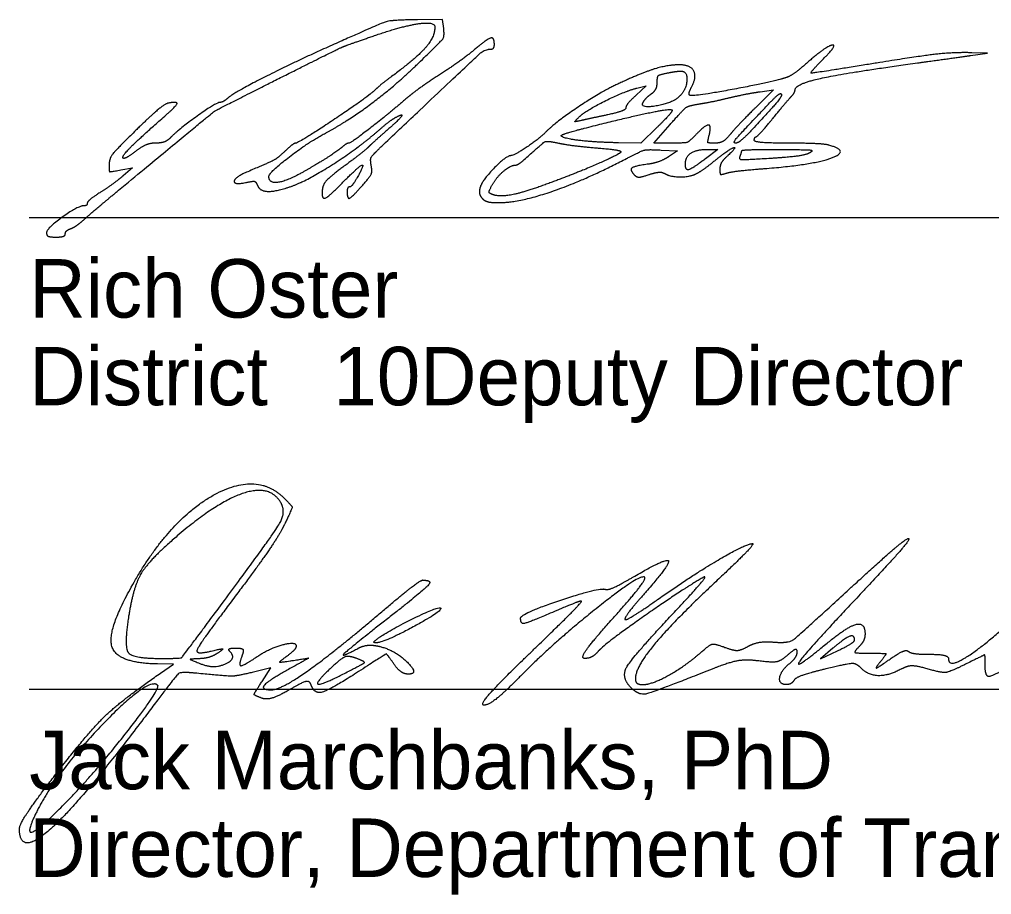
# Model space of a CAD drawing. Extents: x 39.8 to 73.8, y 13 to 35.
# Drawn here: x 64.74 to 67.068, y 18.351 to 20.447 of the extents above; entities that cross this region are included whole.
import ezdxf

# ---------------------------------------------------------------- set-up
doc = ezdxf.new("R2010")
doc.units = 0
doc.layers.add('SH_Data', color=7, linetype='Continuous')
doc.layers.add('SH_Text', color=7, linetype='Continuous')

msp = doc.modelspace()

# ---------------------------------------------------------------- linework, layer by layer
at = {"layer": 'SH_Data'}
for p, q in [((64.763, 19.9729), (68.263, 19.9729)), ((64.763, 18.8435), (68.263, 18.8435))]:
    msp.add_line(p, q, dxfattribs=at)
at = {"layer": 'SH_Text'}
for p, q in [((64.8044, 19.9359), (64.8044, 19.9359)), ((65.2253, 19.0486), (65.2253, 19.0486)), ((65.5906, 18.9587), (65.5906, 18.9587)), ((66.7396, 18.9607), (66.7396, 18.9607)), ((65.9624, 18.9297), (65.9624, 18.9297)), ((65.5458, 18.9171), (65.5458, 18.9171))]:
    msp.add_line(p, q, dxfattribs=at)
for points in [[(65.7556, 20.4251), (65.7531, 20.4469), (65.6931, 20.4462)], [(67.0169, 20.3604), (67.0581, 20.3662), (67.0204, 20.3672)], [(66.2182, 20.2823), (66.2406, 20.2876), (66.2163, 20.2653)], [(66.5132, 20.2738), (66.5457, 20.2786), (66.5019, 20.2352)], [(66.2667, 20.1887), (66.2275, 20.1507), (66.174, 20.1516)], [(66.2994, 20.1507), (66.2585, 20.1507), (66.2977, 20.1952)], [(66.276, 20.1342), (66.3152, 20.1319), (66.2937, 20.1179)], [(66.3869, 20.1357), (66.4121, 20.1357), (66.3826, 20.1134)], [(64.9825, 20.0865), (65.0106, 20.0914), (64.9881, 20.0726)], [(66.6878, 18.941), (66.6583, 18.9154), (66.6989, 18.9351)], [(65.0776, 18.8816), (65.1083, 18.9028), (65.0705, 18.9035)], [(65.3206, 18.8618), (65.3418, 18.8941), (65.3, 18.884)]]:
    msp.add_lwpolyline(points, dxfattribs=at)
for points in [[(65.6931, 20.4462), (65.6306, 20.4455), (65.6042, 20.4373), (65.4681, 20.3762)], [(65.5956, 20.4102), (65.6597, 20.432), (65.7344, 20.442), (65.7344, 20.4287)], [(65.7344, 20.4287), (65.7344, 20.4048), (65.6894, 20.3534), (65.6302, 20.3099)], [(65.6956, 20.3426), (65.7496, 20.395), (65.7578, 20.4062), (65.7556, 20.4251)], [(65.3856, 20.3179), (65.4978, 20.3742), (65.5234, 20.3855), (65.5956, 20.4102)], [(65.8769, 20.3869), (65.8769, 20.4049), (65.8593, 20.4), (65.8276, 20.3732)], [(65.4681, 20.3762), (65.3879, 20.3401), (65.2521, 20.2706), (65.2388, 20.2587)], [(65.6105, 20.1465), (65.8319, 20.3561), (65.8539, 20.3756), (65.8675, 20.3757)], [(65.8276, 20.3732), (65.8114, 20.3595), (65.7745, 20.3331), (65.7456, 20.3144)], [(65.8675, 20.3757), (65.8727, 20.3757), (65.8769, 20.3807), (65.8769, 20.3869)], [(66.6637, 20.3513), (66.7005, 20.3881), (66.671, 20.3828), (66.628, 20.3448)], [(66.7604, 20.3374), (66.64, 20.3178), (66.6314, 20.3191), (66.6637, 20.3513)], [(67.0204, 20.3672), (66.976, 20.3683), (66.8921, 20.3587), (66.7604, 20.3374)], [(66.8902, 20.3428), (66.9372, 20.3493), (66.9942, 20.3572), (67.0169, 20.3604)], [(65.4723, 20.1747), (65.526, 20.2031), (65.6407, 20.2893), (65.6956, 20.3426)], [(66.3195, 20.3382), (66.292, 20.3382), (66.2302, 20.319), (66.1747, 20.2933)], [(66.3495, 20.286), (66.3623, 20.3099), (66.346, 20.3382), (66.3195, 20.3382)], [(66.628, 20.3448), (66.6088, 20.3279), (66.5864, 20.3115), (66.5781, 20.3085)], [(66.5969, 20.2778), (66.5969, 20.2922), (66.7195, 20.3194), (66.8902, 20.3428)], [(64.9769, 20.0377), (65.2015, 20.2237), (65.211, 20.2302), (65.3856, 20.3179)], [(65.6302, 20.3099), (65.6153, 20.2989), (65.5972, 20.284), (65.5899, 20.2768)], [(65.7456, 20.3144), (65.7168, 20.2958), (65.683, 20.2718), (65.6706, 20.2612)], [(66.2669, 20.2964), (66.2669, 20.3099), (66.2722, 20.3148), (66.2903, 20.3185)], [(66.2903, 20.3185), (66.3032, 20.3211), (66.3184, 20.3232), (66.3241, 20.3232)], [(66.3241, 20.3232), (66.3391, 20.3232), (66.3371, 20.2804), (66.3213, 20.2637)], [(66.5781, 20.3085), (66.5507, 20.2984), (66.349, 20.261), (66.3448, 20.2652)], [(66.1747, 20.2933), (66.1327, 20.2739), (66.0242, 20.2015), (65.9985, 20.1758)], [(66.0794, 20.2129), (66.0938, 20.2278), (66.1889, 20.2753), (66.2182, 20.2823)], [(66.2533, 20.2692), (66.2608, 20.2746), (66.2669, 20.2868), (66.2669, 20.2964)], [(66.3448, 20.2652), (66.3425, 20.2675), (66.3447, 20.2768), (66.3495, 20.286)], [(66.5875, 20.2618), (66.5927, 20.2673), (66.5969, 20.2745), (66.5969, 20.2778)], [(65.2388, 20.2587), (65.2323, 20.2529), (65.2237, 20.2482), (65.2197, 20.2482)], [(65.5899, 20.2768), (65.5751, 20.262), (65.4083, 20.1507), (65.401, 20.1507)], [(65.6706, 20.2612), (65.626, 20.2228), (65.5333, 20.1507), (65.5286, 20.1507)], [(66.2163, 20.2653), (66.2029, 20.2531), (66.1919, 20.2397), (66.1919, 20.2356)], [(66.3213, 20.2637), (66.3049, 20.2464), (66.2239, 20.233), (66.2336, 20.2492)], [(66.2336, 20.2492), (66.237, 20.2548), (66.2458, 20.2638), (66.2533, 20.2692)], [(66.3675, 20.2446), (66.3844, 20.2473), (66.4167, 20.2539), (66.4394, 20.2593)], [(66.4394, 20.2593), (66.4621, 20.2647), (66.4953, 20.2712), (66.5132, 20.2738)], [(66.5639, 20.2687), (66.5673, 20.2652), (66.5435, 20.2362), (66.4909, 20.1798)], [(66.5392, 20.2501), (66.5509, 20.2622), (66.5619, 20.2706), (66.5639, 20.2687)], [(66.5444, 20.2107), (66.5629, 20.2334), (66.5823, 20.2564), (66.5875, 20.2618)], [(65.0972, 20.2468), (65.0892, 20.2455), (65.0537, 20.2161), (65.0185, 20.1816)], [(65.0875, 20.2153), (65.1152, 20.2394), (65.1186, 20.2503), (65.0972, 20.2468)], [(65.2197, 20.2482), (65.211, 20.2482), (65.1213, 20.1843), (65.1022, 20.1646)], [(66.0922, 20.1863), (66.189, 20.2111), (66.2985, 20.234), (66.3023, 20.2302)], [(66.1919, 20.2356), (66.1919, 20.2314), (66.1725, 20.2238), (66.1488, 20.2187)], [(66.2977, 20.1952), (66.3301, 20.232), (66.3423, 20.2406), (66.3675, 20.2446)], [(66.5019, 20.2352), (66.4778, 20.2113), (66.4506, 20.1826), (66.4413, 20.1712)], [(66.4547, 20.1507), (66.4469, 20.1507), (66.4683, 20.1759), (66.5392, 20.2501)], [(64.9875, 20.115), (64.9838, 20.1187), (65.0307, 20.1657), (65.0875, 20.2153)], [(65.5994, 20.1809), (65.6138, 20.1936), (65.6319, 20.2075), (65.6397, 20.2118)], [(65.6397, 20.2118), (65.6604, 20.2234), (65.6478, 20.2057), (65.6153, 20.1774)], [(66.0869, 20.2053), (66.0701, 20.2017), (66.0693, 20.2025), (66.0794, 20.2129)], [(66.1488, 20.2187), (66.125, 20.2136), (66.0972, 20.2076), (66.0869, 20.2053)], [(66.3023, 20.2302), (66.3043, 20.2283), (66.2882, 20.2096), (66.2667, 20.1887)], [(66.505, 20.1669), (66.5081, 20.1683), (66.5258, 20.188), (66.5444, 20.2107)], [(66.0373, 20.1677), (66.0353, 20.1697), (66.06, 20.1781), (66.0922, 20.1863)], [(66.3913, 20.1694), (66.3975, 20.1941), (66.3815, 20.1941), (66.358, 20.1693)], [(65.0185, 20.1816), (64.9721, 20.1361), (64.9544, 20.1136), (64.9544, 20.1001)], [(65.1022, 20.1646), (65.0948, 20.1569), (65.0786, 20.1507), (65.0661, 20.1507)], [(65.3369, 20.0707), (65.3369, 20.0802), (65.4327, 20.1538), (65.4723, 20.1747)], [(65.3901, 20.047), (65.4272, 20.0597), (65.5537, 20.1407), (65.5994, 20.1809)], [(65.6153, 20.1774), (65.6007, 20.1648), (65.5831, 20.1489), (65.5762, 20.1422)], [(65.9985, 20.1758), (65.9832, 20.1605), (65.9239, 20.1207), (65.9164, 20.1207)], [(66.174, 20.1516), (66.1188, 20.1526), (66.0436, 20.1614), (66.0373, 20.1677)], [(66.358, 20.1693), (66.3434, 20.1539), (66.3332, 20.1507), (66.2994, 20.1507)], [(66.4055, 20.1507), (66.3891, 20.1507), (66.3872, 20.1531), (66.3913, 20.1694)], [(66.4413, 20.1712), (66.431, 20.1587), (66.4171, 20.1507), (66.4055, 20.1507)], [(66.4909, 20.1798), (66.4759, 20.1638), (66.4596, 20.1507), (66.4547, 20.1507)], [(66.4994, 20.1575), (66.4994, 20.1613), (66.5019, 20.1655), (66.505, 20.1669)], [(65.0661, 20.1507), (65.0531, 20.1507), (65.0323, 20.1422), (65.0174, 20.1309)], [(65.401, 20.1507), (65.3984, 20.1507), (65.3871, 20.1422), (65.376, 20.1319)], [(65.5147, 20.1431), (65.5, 20.1308), (65.4523, 20.1002), (65.4155, 20.0797)], [(65.5286, 20.1507), (65.5259, 20.1507), (65.5197, 20.1472), (65.5147, 20.1431)], [(65.5762, 20.1422), (65.5693, 20.1355), (65.5448, 20.116), (65.5218, 20.099)], [(65.5821, 20.0969), (65.5792, 20.1122), (65.5849, 20.1223), (65.6105, 20.1465)], [(65.9486, 20.1114), (65.9928, 20.1516), (66.0037, 20.1567), (66.0325, 20.1505)], [(66.0325, 20.1505), (66.048, 20.1472), (66.0888, 20.1421), (66.1232, 20.1392)], [(66.1232, 20.1392), (66.1576, 20.1364), (66.1829, 20.1316), (66.1794, 20.1286)], [(66.4079, 20.1112), (66.4405, 20.1376), (66.4598, 20.1422), (66.4319, 20.117)], [(66.58, 20.1506), (66.5357, 20.1506), (66.4994, 20.1538), (66.4994, 20.1575)], [(66.5294, 20.0903), (66.6406, 20.0989), (66.7293, 20.1321), (66.6778, 20.1459)], [(66.6778, 20.1459), (66.6684, 20.1484), (66.6244, 20.1505), (66.58, 20.1506)], [(65.0174, 20.1309), (65.0032, 20.12), (64.9897, 20.1129), (64.9875, 20.115)], [(65.376, 20.1319), (65.3568, 20.1141), (65.3423, 20.1061), (65.2863, 20.0823)], [(65.9164, 20.1207), (65.9054, 20.1207), (65.8484, 20.0622), (65.8431, 20.0456)], [(66.1794, 20.1286), (66.1699, 20.1205), (66.068, 20.0767), (66.0044, 20.0533)], [(66.1937, 20.114), (66.2285, 20.1322), (66.2442, 20.136), (66.276, 20.1342)], [(66.2937, 20.1179), (66.282, 20.1102), (66.2592, 20.1022), (66.2432, 20.1)], [(66.3344, 20.1008), (66.3344, 20.1181), (66.3608, 20.1357), (66.3869, 20.1357)], [(66.4319, 20.117), (66.4237, 20.1095), (66.4169, 20.0967), (66.4169, 20.0886)], [(66.5396, 20.1141), (66.4761, 20.1102), (66.4624, 20.1111), (66.4655, 20.1193)], [(66.4655, 20.1193), (66.4676, 20.1249), (66.4694, 20.1308), (66.4694, 20.1325)], [(66.4694, 20.1325), (66.4694, 20.1343), (66.509, 20.1356), (66.5575, 20.1354)], [(66.6316, 20.1271), (66.6239, 20.1226), (66.5825, 20.1168), (66.5396, 20.1141)], [(66.5575, 20.1354), (66.6246, 20.1353), (66.6423, 20.1333), (66.6316, 20.1271)], [(64.9544, 20.1001), (64.9544, 20.0827), (64.9562, 20.0818), (64.9825, 20.0865)], [(65.5218, 20.099), (65.4819, 20.0695), (65.4644, 20.0488), (65.4644, 20.0312)], [(65.5143, 20.0569), (65.5527, 20.0959), (65.5668, 20.1005), (65.5484, 20.0682)], [(65.5618, 20.0504), (65.5794, 20.0705), (65.5848, 20.0828), (65.5821, 20.0969)], [(65.8704, 20.0481), (65.8801, 20.0669), (65.9144, 20.0975), (65.9261, 20.0979)], [(65.8875, 20.0082), (65.937, 20.0082), (66.0964, 20.0632), (66.1937, 20.114)], [(65.9261, 20.0979), (65.9305, 20.098), (65.9406, 20.1041), (65.9486, 20.1114)], [(66.2432, 20.1), (66.2117, 20.0958), (66.2007, 20.0864), (66.2128, 20.0742)], [(66.3826, 20.1134), (66.3506, 20.0892), (66.3344, 20.0849), (66.3344, 20.1008)], [(66.3606, 20.0776), (66.3689, 20.0817), (66.3902, 20.0969), (66.4079, 20.1112)], [(64.9881, 20.0726), (64.9758, 20.0622), (64.9513, 20.0445), (64.9338, 20.0332)], [(65.2863, 20.0823), (65.255, 20.0691), (65.2529, 20.05), (65.2834, 20.0567)], [(65.4155, 20.0797), (65.3784, 20.059), (65.3369, 20.0542), (65.3369, 20.0707)], [(65.5484, 20.0682), (65.5414, 20.0559), (65.5331, 20.0457), (65.53, 20.0457)], [(66.2128, 20.0742), (66.2181, 20.069), (66.2291, 20.0694), (66.2473, 20.0754)], [(66.2473, 20.0754), (66.262, 20.0802), (66.278, 20.0818), (66.2827, 20.0789)], [(66.2827, 20.0789), (66.2968, 20.0702), (66.3444, 20.0694), (66.3606, 20.0776)], [(66.4169, 20.0886), (66.4169, 20.0768), (66.4202, 20.0749), (66.4338, 20.0791)], [(66.4338, 20.0791), (66.443, 20.0819), (66.4861, 20.087), (66.5294, 20.0903)], [(65.2834, 20.0567), (65.2991, 20.0601), (65.3062, 20.0583), (65.3094, 20.0498)], [(65.3094, 20.0498), (65.3148, 20.0357), (65.3536, 20.0344), (65.3901, 20.047)], [(65.4644, 20.0312), (65.4644, 20.015), (65.4819, 20.024), (65.5143, 20.0569)], [(65.5244, 20.0344), (65.5244, 20.0162), (65.5362, 20.0213), (65.5618, 20.0504)], [(65.53, 20.0457), (65.5269, 20.0457), (65.5244, 20.0406), (65.5244, 20.0344)], [(65.8431, 20.0456), (65.8404, 20.037), (65.8422, 20.0251), (65.8472, 20.0191)], [(65.8713, 20.028), (65.8642, 20.031), (65.864, 20.0358), (65.8704, 20.0481)], [(66.0044, 20.0533), (65.9471, 20.0323), (65.8881, 20.0211), (65.8713, 20.028)], [(64.8944, 19.9679), (64.9047, 19.9773), (64.9418, 20.0087), (64.9769, 20.0377)], [(64.9338, 20.0332), (64.9162, 20.0219), (64.9019, 20.01), (64.9019, 20.0067)], [(64.8943, 20.0007), (64.8801, 20.0007), (64.8044, 19.9461), (64.8044, 19.9359)], [(64.9019, 20.0067), (64.9019, 20.0034), (64.8985, 20.0007), (64.8943, 20.0007)], [(65.8472, 20.0191), (65.8524, 20.0127), (65.8693, 20.0082), (65.8875, 20.0082)], [(64.8625, 19.946), (64.8697, 19.9487), (64.8841, 19.9586), (64.8944, 19.9679)], [(64.8044, 19.9359), (64.8044, 19.9295), (64.8129, 19.9257), (64.8269, 19.9257)], [(64.8269, 19.9257), (64.8393, 19.9257), (64.8494, 19.9291), (64.8494, 19.9334)], [(64.8494, 19.9334), (64.8494, 19.9377), (64.8553, 19.9433), (64.8625, 19.946)], [(65.014, 19.0993), (65.1002, 19.2497), (65.3083, 19.3657), (65.374, 19.3001)], [(65.365, 19.2909), (65.3391, 19.3329), (65.213, 19.2918), (65.1176, 19.2101)], [(65.374, 19.3001), (65.3928, 19.2813), (65.3928, 19.2763), (65.3745, 19.2378)], [(65.2253, 19.0486), (65.3466, 19.212), (65.379, 19.2682), (65.365, 19.2909)], [(65.3745, 19.2378), (65.3635, 19.2148), (65.3118, 19.1393), (65.2596, 19.0699)], [(65.1176, 19.2101), (65.051, 19.1531), (65.0122, 19.089), (65.0011, 19.0177)], [(66.2677, 19.0578), (66.3482, 19.1144), (66.4796, 19.1917), (66.4953, 19.1917)], [(66.4953, 19.1917), (66.5001, 19.1917), (66.4588, 19.149), (66.4035, 19.0969)], [(66.722, 19.0782), (66.797, 19.1473), (66.863, 19.2039), (66.8687, 19.204)], [(66.8687, 19.204), (66.8745, 19.2041), (66.8224, 19.1439), (66.7531, 19.0703)], [(66.2087, 19.1113), (66.2875, 19.1575), (66.2997, 19.1442), (66.2405, 19.0769)], [(65.0705, 18.9035), (64.9726, 18.9052), (64.9491, 18.9863), (65.014, 19.0993)], [(65.6041, 19.0258), (65.6545, 19.0687), (65.7, 19.1039), (65.7052, 19.104)], [(65.7052, 19.104), (65.7301, 19.1045), (65.7067, 19.0789), (65.6208, 19.0116)], [(66.2368, 19.1111), (66.2272, 19.1207), (66.0175, 18.9537), (65.9396, 18.8745)], [(66.3771, 19.1106), (66.328, 19.0828), (66.1397, 18.9506), (66.1265, 18.9347)], [(66.1431, 19.0821), (66.1487, 19.0803), (66.1782, 19.0934), (66.2087, 19.1113)], [(66.159, 19.0107), (66.2053, 19.0624), (66.2403, 19.1076), (66.2368, 19.1111)], [(66.4035, 19.0969), (66.3038, 19.0032), (66.2146, 18.8951), (66.2146, 18.8681)], [(66.3119, 19.0317), (66.358, 19.0809), (66.3874, 19.1165), (66.3771, 19.1106)], [(65.2596, 19.0699), (65.2073, 19.0006), (65.1646, 18.9399), (65.1646, 18.9351)], [(65.9398, 19.0135), (65.94, 19.0241), (66.1274, 19.0872), (66.1431, 19.0821)], [(66.2405, 19.0769), (66.2125, 19.0451), (66.1896, 19.0154), (66.1896, 19.011)], [(66.547, 18.9558), (66.5804, 18.953), (66.6039, 18.9694), (66.722, 19.0782)], [(66.7531, 19.0703), (66.6236, 18.9328), (66.5915, 18.8855), (66.6737, 18.9532)], [(65.0791, 18.9167), (65.1258, 18.9167), (65.1304, 18.9208), (65.2253, 19.0486)], [(65.9624, 18.9297), (66.0334, 18.9981), (66.0888, 19.0542), (66.0853, 19.0542)], [(66.0853, 19.0542), (66.0819, 19.0542), (66.0529, 19.0429), (66.0208, 19.0292)], [(66.1896, 19.011), (66.1896, 19.0065), (66.2247, 19.0276), (66.2677, 19.0578)], [(65.3427, 18.8417), (65.3658, 18.8417), (65.4918, 18.9305), (65.6041, 19.0258)], [(65.5906, 18.9587), (65.611, 18.9766), (65.743, 19.0423), (65.7482, 19.0372)], [(65.7482, 19.0372), (65.7544, 19.031), (65.6118, 18.9542), (65.5941, 18.9542)], [(66.0208, 19.0292), (65.9582, 19.0023), (65.9395, 18.9987), (65.9398, 19.0135)], [(66.2048, 18.8461), (66.1796, 18.8713), (66.2085, 18.9214), (66.3119, 19.0317)], [(66.9646, 18.9151), (66.9646, 18.8923), (67.0599, 18.9538), (67.1302, 19.022)], [(65.0011, 19.0177), (64.9896, 18.9444), (65.0111, 18.9167), (65.0791, 18.9167)], [(65.6208, 19.0116), (65.5276, 18.9386), (65.5061, 18.9171), (65.55, 18.9406)], [(66.0932, 18.9167), (66.0829, 18.9167), (66.1118, 18.9579), (66.159, 19.0107)], [(66.6737, 18.9532), (66.7221, 18.9931), (66.7646, 19.0035), (66.7646, 18.9754)], [(66.7646, 18.9754), (66.7646, 18.9665), (66.7578, 18.9524), (66.7496, 18.9442)], [(65.3087, 18.921), (65.3375, 18.9408), (65.4021, 18.9583), (65.4021, 18.9464)], [(65.5941, 18.9542), (65.5893, 18.9542), (65.5877, 18.9562), (65.5906, 18.9587)], [(66.3721, 18.9317), (66.3924, 18.9497), (66.4052, 18.9523), (66.429, 18.9433)], [(66.484, 18.9454), (66.4974, 18.9529), (66.5257, 18.9576), (66.547, 18.9558)], [(66.7396, 18.9607), (66.7396, 18.9742), (66.7155, 18.965), (66.6878, 18.941)], [(66.6989, 18.9351), (66.7213, 18.9459), (66.7396, 18.9575), (66.7396, 18.9607)], [(65.1646, 18.9351), (65.1646, 18.9304), (65.18, 18.93), (65.1989, 18.9344)], [(65.2146, 18.9297), (65.2043, 18.9227), (65.1846, 18.9166), (65.1708, 18.9161)], [(65.175, 18.9034), (65.2049, 18.8914), (65.2611, 18.916), (65.2437, 18.9334)], [(65.1989, 18.9344), (65.2244, 18.9404), (65.2285, 18.9391), (65.2146, 18.9297)], [(65.2437, 18.9334), (65.2391, 18.9379), (65.2454, 18.9417), (65.2576, 18.9417)], [(65.2576, 18.9417), (65.2721, 18.9417), (65.2773, 18.9352), (65.2725, 18.9229)], [(65.4021, 18.9464), (65.4021, 18.9419), (65.3923, 18.931), (65.3804, 18.9223)], [(65.55, 18.9406), (65.5627, 18.9473), (65.5866, 18.9494), (65.6032, 18.9452)], [(65.6362, 18.9038), (65.6193, 18.9279), (65.6173, 18.9274), (65.5515, 18.8851)], [(65.6032, 18.9452), (65.6393, 18.9361), (65.6976, 18.8792), (65.6709, 18.8792)], [(65.8521, 18.8049), (65.8418, 18.805), (65.8914, 18.8612), (65.9624, 18.9297)], [(66.1265, 18.9347), (66.1182, 18.9248), (66.1033, 18.9167), (66.0932, 18.9167)], [(66.2326, 18.8542), (66.2543, 18.8542), (66.3357, 18.8994), (66.3721, 18.9317)], [(66.429, 18.9433), (66.4492, 18.9356), (66.468, 18.9363), (66.484, 18.9454)], [(66.6021, 18.9326), (66.6021, 18.9397), (66.5919, 18.9363), (66.5795, 18.9251)], [(66.5833, 18.9042), (66.5936, 18.9127), (66.6021, 18.9255), (66.6021, 18.9326)], [(66.7496, 18.9442), (66.7379, 18.9325), (66.7438, 18.9292), (66.7761, 18.9292)], [(66.7761, 18.9292), (66.8136, 18.9292), (66.816, 18.9271), (66.8005, 18.9078)], [(66.8222, 18.9136), (66.8436, 18.9286), (66.8643, 18.9377), (66.8683, 18.9338)], [(66.8683, 18.9338), (66.8722, 18.9299), (66.8955, 18.9267), (66.92, 18.9267)], [(65.1708, 18.9161), (65.1484, 18.9152), (65.1488, 18.9139), (65.175, 18.9034)], [(65.2725, 18.9229), (65.2636, 18.8996), (65.2765, 18.899), (65.3087, 18.921)], [(65.3804, 18.9223), (65.3615, 18.9085), (65.3635, 18.9072), (65.3961, 18.9121)], [(65.3961, 18.9121), (65.4328, 18.9177), (65.4327, 18.9175), (65.3873, 18.8923)], [(65.5458, 18.9171), (65.5286, 18.9234), (65.5121, 18.9183), (65.4927, 18.9005)], [(65.5177, 18.8808), (65.5641, 18.9044), (65.5676, 18.909), (65.5458, 18.9171)], [(65.6709, 18.8792), (65.6613, 18.8792), (65.6457, 18.8903), (65.6362, 18.9038)], [(66.51, 18.9107), (66.4808, 18.9144), (66.4409, 18.908), (66.4044, 18.8935)], [(66.5795, 18.9251), (66.5638, 18.9109), (66.5426, 18.9065), (66.51, 18.9107)], [(66.5763, 18.8542), (66.558, 18.8542), (66.5625, 18.8869), (66.5833, 18.9042)], [(66.755, 18.8937), (66.7439, 18.9049), (66.7238, 18.9044), (66.6706, 18.8916)], [(66.8005, 18.9078), (66.7884, 18.8928), (66.7949, 18.8945), (66.8222, 18.9136)], [(66.92, 18.9267), (66.9445, 18.9267), (66.9646, 18.9215), (66.9646, 18.9151)], [(67.0521, 18.9026), (67.0521, 18.9255), (67.051, 18.9255), (67.0049, 18.9027)], [(64.8267, 18.6394), (64.9043, 18.7399), (64.9844, 18.8172), (65.0776, 18.8816)], [(65.1588, 18.8817), (65.1254, 18.885), (65.1137, 18.8745), (65.037, 18.7729)], [(65.3, 18.884), (65.2597, 18.8743), (65.2374, 18.8739), (65.1588, 18.8817)], [(65.3873, 18.8923), (65.3362, 18.8641), (65.3164, 18.8417), (65.3427, 18.8417)], [(65.5515, 18.8851), (65.4827, 18.8407), (65.4452, 18.831), (65.4371, 18.8553)], [(65.4927, 18.9005), (65.4484, 18.86), (65.4597, 18.8512), (65.5177, 18.8808)], [(66.4044, 18.8935), (66.2584, 18.8359), (66.2233, 18.8275), (66.2048, 18.8461)], [(66.6706, 18.8916), (66.6323, 18.8824), (66.598, 18.8702), (66.5945, 18.8645)], [(66.8513, 18.8912), (66.8205, 18.8748), (66.7727, 18.876), (66.755, 18.8937)], [(66.9158, 18.8913), (66.8889, 18.899), (66.8658, 18.899), (66.8513, 18.8912)], [(67.0049, 18.9027), (66.9675, 18.8842), (66.9489, 18.8818), (66.9158, 18.8913)], [(67.114, 18.8996), (67.069, 18.873), (67.0521, 18.8738), (67.0521, 18.9026)], [(65.3194, 18.8217), (65.3012, 18.8287), (65.3013, 18.8324), (65.3206, 18.8618)], [(65.4371, 18.8553), (65.4342, 18.8639), (65.415, 18.8587), (65.3859, 18.8415)], [(65.9396, 18.8745), (65.9018, 18.836), (65.8624, 18.8047), (65.8521, 18.8049)], [(66.2146, 18.8681), (66.2146, 18.8604), (66.2227, 18.8542), (66.2326, 18.8542)], [(66.5945, 18.8645), (66.591, 18.8588), (66.5828, 18.8542), (66.5763, 18.8542)], [(65.0705, 18.8524), (65.0496, 18.8733), (64.8311, 18.6476), (64.7848, 18.5573)], [(64.8549, 18.576), (64.9225, 18.6451), (65.0782, 18.8447), (65.0705, 18.8524)], [(65.3859, 18.8415), (65.3603, 18.8264), (65.3304, 18.8175), (65.3194, 18.8217)], [(65.037, 18.7729), (64.8847, 18.5708), (64.7396, 18.4422), (64.7396, 18.5092)], [(64.7396, 18.5092), (64.7396, 18.5188), (64.7788, 18.5774), (64.8267, 18.6394)], [(64.7848, 18.5573), (64.7535, 18.4963), (64.7851, 18.5048), (64.8549, 18.576)]]:
    msp.add_open_spline(points, degree=2, dxfattribs=at)

# ---------------------------------------------------------------- texts
for s, p in [('Rich Oster', (64.763, 19.7329)), ('District       Deputy Director', (64.763, 19.5229)), ('              10', (64.763, 19.5229)), ('Jack Marchbanks, PhD', (64.763, 18.6035)), ('Director, Department of Transportation', (64.763, 18.3935))]:
    msp.add_text(s, height=0.14, dxfattribs=at).set_placement(p)

doc.saveas('drawing.dxf')
